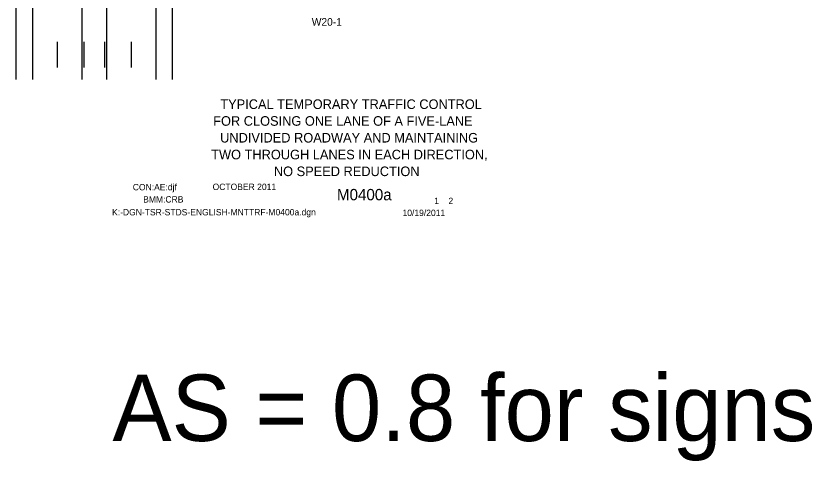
# Model space of a CAD drawing. Extents: x 16765 to 18475, y 6981 to 8262.
# Drawn here: x 16977 to 17751, y 6981 to 7414 of the extents above; entities that cross this region are included whole.
import ezdxf

# ---------------------------------------------------------------- set-up
doc = ezdxf.new("R2010")
doc.units = 0
for name, color, linetype in [('ALI_LEGAL_EX', 7, 'Continuous'), ('BORDER_SIGNAL_WO', 7, 'Continuous'), ('PAVT_EDGE_EX', 7, 'Continuous'), ('TRAFFIC_SIGNS_PR', 7, 'Continuous')]:
    doc.layers.add(name, color=color, linetype=linetype)

msp = doc.modelspace()

# ---------------------------------------------------------------- linework, layer by layer
at = {"layer": 'ALI_LEGAL_EX'}
for points in [[(17017.08, 7388.47), (17017.08, 7363.47)], [(17043.08, 7388.47), (17043.08, 7363.47)], [(17063.08, 7388.47), (17063.08, 7363.47)], [(17089.08, 7388.47), (17089.08, 7363.47)]]:
    msp.add_lwpolyline(points, dxfattribs=at)
at = {"layer": 'PAVT_EDGE_EX'}
for p, q in [((16977.08, 8196.54), (16977.08, 7351.89)), ((16993.08, 8196.54), (16993.08, 7351.89)), ((17041.08, 8196.54), (17041.08, 7351.89)), ((17113.08, 8196.54), (17113.08, 7351.89)), ((17129.08, 8196.54), (17129.08, 7351.89)), ((17065.08, 7615.49), (17065.08, 7351.89))]:
    msp.add_line(p, q, dxfattribs=at)

# ---------------------------------------------------------------- texts
at = {"layer": 'BORDER_SIGNAL_WO'}
for s, height, p in [('TYPICAL TEMPORARY TRAFFIC CONTROL', 9.3, (17175.79, 7323.31)), ('FOR CLOSING ONE LANE OF A FIVE-LANE', 9.3, (17168.86, 7307.01)), ('UNDIVIDED ROADWAY AND MAINTAINING', 9.3, (17175.61, 7290.71)), ('TWO THROUGH LANES IN EACH DIRECTION,', 9.3, (17166.92, 7274.41)), ('NO SPEED REDUCTION', 9.3, (17227.88, 7258.11)), ('CON:AE:djf', 6.2, (17090.69, 7244.31)), ('    OCTOBER 2011    ', 6.2, (17159.08, 7244.59)), ('    M0400a   ', 11, (17272.86, 7234.63)), ('BMM:CRB   ', 6.2, (17100.81, 7232.42)), (' 1    2 ', 6.2, (17381.45, 7230.95)), ('K:-DGN-TSR-STDS-ENGLISH-MNTTRF-M0400a.dgn        ', 6.2, (17070.55, 7219.96)), ('10/19/2011    ', 6.2, (17352.93, 7219.38)), ('AS = 0.8 for signs', 64.512, (17070.9, 7000.82))]:
    msp.add_text(s, height=height, dxfattribs=at).set_placement(p)
at = {"layer": 'TRAFFIC_SIGNS_PR'}
msp.add_text('W20-1', height=7.449, dxfattribs=at).set_placement((17264.68, 7404.16))

doc.saveas('drawing.dxf')
